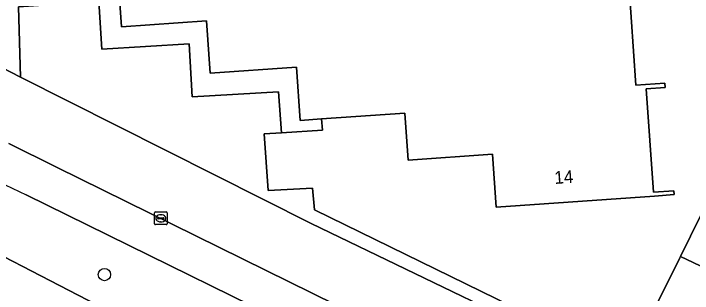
# Model space of a CAD drawing. Extents: x 160102 to 160934, y 382045 to 382923.
# Drawn here: x 160192.3 to 160245.8, y 382138.3 to 382160.4 of the extents above; entities that cross this region are included whole.
import ezdxf

# ---------------------------------------------------------------- set-up
doc = ezdxf.new("R2010")
doc.units = 0
for name, color, linetype in [('IMGEO_Berm_groen', 7, 'Continuous'), ('IMGEO_Boom', 7, 'Continuous'), ('IMGEO_Erf', 7, 'Continuous'), ('IMGEO_Fietspad_open', 7, 'Continuous'), ('IMGEO_Groenvoorziening', 7, 'Continuous'), ('IMGEO_Kolk', 7, 'Continuous'), ('IMGEO_Pand', 7, 'Continuous'), ('IMGEO_Pand_nummerreeks', 7, 'Continuous'), ('IMGEO_Rijbaan_regionaal_gesloten', 7, 'Continuous'), ('IMGEO_Voetpad_open', 7, 'Continuous')]:
    doc.layers.add(name, color=color, linetype=linetype)

msp = doc.modelspace()

# ---------------------------------------------------------------- linework, layer by layer
at = {"layer": 'IMGEO_Berm_groen'}
for points in [[(160233.353, 382126.334), (160220.711, 382132.524), (160193.242, 382146.047)], [(160186.295, 382143.828), (160198.828, 382137.367), (160221.422, 382126.274)]]:
    msp.add_lwpolyline(points, dxfattribs=at)
msp.add_arc((160216.684, 382196.904), 56, 225.3649, 245.2534, dxfattribs=at)
at = {"layer": 'IMGEO_Boom'}
msp.add_circle((160199.417, 382139.751), 0.489, dxfattribs=at)
at = {"layer": 'IMGEO_Erf'}
for points in [[(160240.768, 382162.786), (160241.34, 382154.696), (160243.62, 382154.857), (160243.644, 382154.524), (160242.153, 382154.419), (160242.73, 382146.262), (160244.321, 382146.375), (160244.343, 382146.064), (160242.804, 382145.955), (160230.327, 382145.073), (160230.031, 382149.264), (160223.362, 382148.793), (160223.1, 382152.506), (160216.549, 382152.043), (160216.623, 382151.159), (160213.37, 382150.941), (160212.003, 382150.85), (160212.323, 382146.381), (160215.839, 382146.572), (160215.985, 382144.858), (160239.856, 382133.189)], [(160242.613, 382136.693), (160244.804, 382141.067), (160244.865, 382141.191), (160254.441, 382160.714)]]:
    msp.add_lwpolyline(points, dxfattribs=at)
at = {"layer": 'IMGEO_Fietspad_open'}
for points in [[(160238.14, 382127.302), (160221.309, 382135.576), (160195.642, 382148.235), (160191.869, 382150.101)], [(160193.242, 382146.047), (160220.711, 382132.524), (160233.353, 382126.334)]]:
    msp.add_lwpolyline(points, dxfattribs=at)
msp.add_arc((160216.684, 382196.904), 56, 225.3649, 245.2534, dxfattribs=at)
at = {"layer": 'IMGEO_Groenvoorziening'}
msp.add_lwpolyline([(160192.787, 382155.341), (160215.732, 382143.774), (160240.256, 382131.952), (160242.613, 382136.693), (160241.823, 382137.133), (160239.856, 382133.189), (160215.985, 382144.858), (160215.839, 382146.572), (160212.323, 382146.381), (160212.003, 382150.85), (160213.37, 382150.941), (160213.137, 382154.185), (160206.329, 382153.786), (160206.088, 382157.973), (160199.216, 382157.542), (160198.982, 382161.298), (160192.632, 382160.887)], close=True, dxfattribs=at)
at = {"layer": 'IMGEO_Kolk'}
for p, q in [((160203.366, 382143.771), (160203.366, 382144.623)), ((160203.441, 382144.697), (160204.293, 382144.697)), ((160203.854, 382144.477), (160203.879, 382144.477)), ((160204.367, 382144.623), (160204.367, 382143.771)), ((160203.625, 382144.191), (160203.625, 382144.203)), ((160204.063, 382144.154), (160203.665, 382144.154)), ((160203.668, 382144.24), (160204.066, 382144.24)), ((160203.877, 382143.917), (160203.852, 382143.917)), ((160204.109, 382144.203), (160204.109, 382144.191)), ((160204.293, 382143.697), (160203.441, 382143.697))]:
    msp.add_line(p, q, dxfattribs=at)
for points in [[(160203.366, 382143.771), (160203.366, 382144.623)], [(160203.441, 382144.697), (160204.293, 382144.697)], [(160204.367, 382144.623), (160204.367, 382143.771)], [(160204.293, 382143.697), (160203.441, 382143.697)]]:
    msp.add_lwpolyline(points, dxfattribs=at)
for centre, radius, start, end in [((160203.443, 382144.621), 0.0765, 91.552, 178.448), ((160203.443, 382144.621), 0.0765, 91.552, 178.448), ((160204.291, 382144.621), 0.0765, 1.552, 88.448), ((160204.291, 382144.621), 0.0765, 1.552, 88.448), ((160203.443, 382143.773), 0.0765, 181.552, 268.448), ((160203.443, 382143.773), 0.0765, 181.552, 268.448), ((160203.665, 382144.2), 0.0403, 85.8775, 175.7526), ((160203.662, 382144.19), 0.0366, 178.938, 274.7102), ((160204.066, 382144.197), 0.043, 264.8664, 352.4533), ((160204.07, 382144.202), 0.0386, 1.7309, 96.639), ((160204.291, 382143.773), 0.0765, 271.552, 358.448), ((160204.291, 382143.773), 0.0765, 271.552, 358.448)]:
    msp.add_arc(centre, radius, start, end, dxfattribs=at)
for centre, major_axis, ratio, start_param, end_param in [((160203.853, 382144.197), (-0.387, 0.002), 0.722429, 4.712389, 7.853982), ((160203.878, 382144.197), (-0.39, 0.002), 0.717154, 1.570796, 4.712389)]:
    msp.add_ellipse(centre, major_axis=major_axis, ratio=ratio, start_param=start_param, end_param=end_param, dxfattribs=at)
at = {"layer": 'IMGEO_Pand'}
msp.add_lwpolyline([(160200.468, 382163.473), (160200.762, 382159.311), (160207.466, 382159.785), (160207.759, 382155.64), (160214.554, 382156.12), (160214.85, 382151.923), (160216.549, 382152.043), (160223.1, 382152.506), (160223.362, 382148.793), (160230.031, 382149.264), (160230.327, 382145.073), (160242.804, 382145.955), (160244.343, 382146.064), (160244.321, 382146.375), (160242.73, 382146.262), (160242.153, 382154.419), (160243.644, 382154.524), (160243.62, 382154.857), (160241.34, 382154.696), (160240.768, 382162.786)], dxfattribs=at)
at = {"layer": 'IMGEO_Rijbaan_regionaal_gesloten'}
msp.add_lwpolyline([(160221.422, 382126.274), (160198.828, 382137.367), (160186.295, 382143.828)], dxfattribs=at)
at = {"layer": 'IMGEO_Voetpad_open'}
for points in [[(160193.379, 382168.398), (160192.643, 382168.346), (160192.118, 382175.773), (160189.409, 382175.582), (160190.575, 382156.456), (160192.787, 382155.341), (160192.632, 382160.887), (160198.982, 382161.298), (160199.216, 382157.542), (160206.088, 382157.973), (160206.329, 382153.786), (160213.137, 382154.185), (160213.37, 382150.941), (160216.623, 382151.159), (160216.549, 382152.043), (160214.85, 382151.923), (160214.554, 382156.12), (160207.759, 382155.64), (160207.466, 382159.785), (160200.762, 382159.311), (160200.468, 382163.473), (160193.761, 382162.999)], [(160257.737, 382158.363), (160257.201, 382158.663), (160257.341, 382158.929), (160256.516, 382159.349), (160256.631, 382159.628), (160254.441, 382160.714), (160244.865, 382141.191), (160248.457, 382139.473), (160248.272, 382139.097), (160249.856, 382138.355), (160251.048, 382140.65), (160249.432, 382141.458)], [(160248.272, 382139.097), (160248.457, 382139.473), (160244.865, 382141.191), (160244.804, 382141.067), (160242.613, 382136.693), (160246.188, 382134.854)]]:
    msp.add_lwpolyline(points, close=True, dxfattribs=at)
for points in [[(160215.732, 382143.774), (160192.787, 382155.341), (160190.575, 382156.456)], [(160191.869, 382150.101), (160195.642, 382148.235), (160221.309, 382135.576), (160238.14, 382127.302), (160238.271, 382127.238)], [(160245.739, 382129.78), (160240.256, 382131.952), (160215.732, 382143.774)]]:
    msp.add_lwpolyline(points, dxfattribs=at)

# ---------------------------------------------------------------- texts
at = {"layer": 'IMGEO_Pand_nummerreeks'}
msp.add_text('14', height=1, rotation=4.0451, dxfattribs=at).set_placement((160234.941, 382146.902))

doc.saveas('drawing.dxf')
